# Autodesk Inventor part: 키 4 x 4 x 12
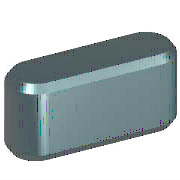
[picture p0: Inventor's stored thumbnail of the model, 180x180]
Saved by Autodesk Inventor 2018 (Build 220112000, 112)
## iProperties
IsCustomPart: 1
Created: 2012-02
Part Number: 키 4 x 4 x 12
Material: 강철, 연강
Description: 키 및 해당 키홈
Document SubType Name: Modeling
Standard: KS B 1311
Designer: mduedu
Standards Organization: KS
Language: ko-KR
Size Designation: 4 x 4 x 12
Categories: <MemberInstance><Categories><Category DisplayName="샤프트 부품" InternalName="7f7aeb1f-a693-4053-b835-cee3144e0d98" Mnemonic="SHFT"><Category DisplayName="키" Interna
Density: 1 g/cm^3
Appearance: 노란색
Author: mduedu
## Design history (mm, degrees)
workplane "Work Plane1"
workplane "Work Plane2"
sketch "스케치1"
  geometry: L1 (2, 2)-(10, 2); L2 (10, -2)-(2, -2); L3 (0, 9.4)-(0, -7.4) reference; L4 (-5, 0)-(30, 0) reference; L5 (12, 0)-(12, 7); A1 r 2 centre (2, 0) between (2, 2) and (2, -2); A2 r 2 centre (10, 0) between (10, -2) and (10, 2)
  constraints: 6 end point, 5 point on circle, 4 tangent, 3 point on line, 2 centre point, 1 horizontal, 1 parallel, 1 perpendicular
  dimensions: "d0" = 2 radius of A1 (= 0.5 x PB); "d13" = 2 radius of A2 (= 0.5 x PB); "d14" = 12 distance between parallel lines of L5 L3 (= NLG)
extrude "본체1" new body sketch "스케치1" taper "d3" = 0 deg; stored distance "d4" = 10
workplane "Work Plane3"
body "Solid1"
chamfer "모따기1" distance "d8" = 0.25 (= PHH); stored, may be unused: second distance "d9" = 0.25 (= PHH), angle "d15" = 45 deg
other parameters: "d1" = -2.5 (= -PNT), "d2" = 1.5 (= PH - PNT), "NLG" = 12 [user parameter; used in 3 equation terms], "PB" = 4 [user parameter; used in 2 equation terms], "PNT" = 2.5 [user parameter; used in 2 equation terms], "PH" = 4 [user parameter; used in 1 equation term], "PHH" = 0.25 [user parameter; used in 2 equation terms], "d10" = 0, "d16" = 0, "d17" = 0, "d18" = 0, "PLB2" = 12 (= NLG) [user parameter], "WDMAX" = 12 [user parameter], "PLB1" = 12 (= NLG) [user parameter], "RR" = 0.08 [user parameter], "PUEB" = 1.8 [user parameter]
